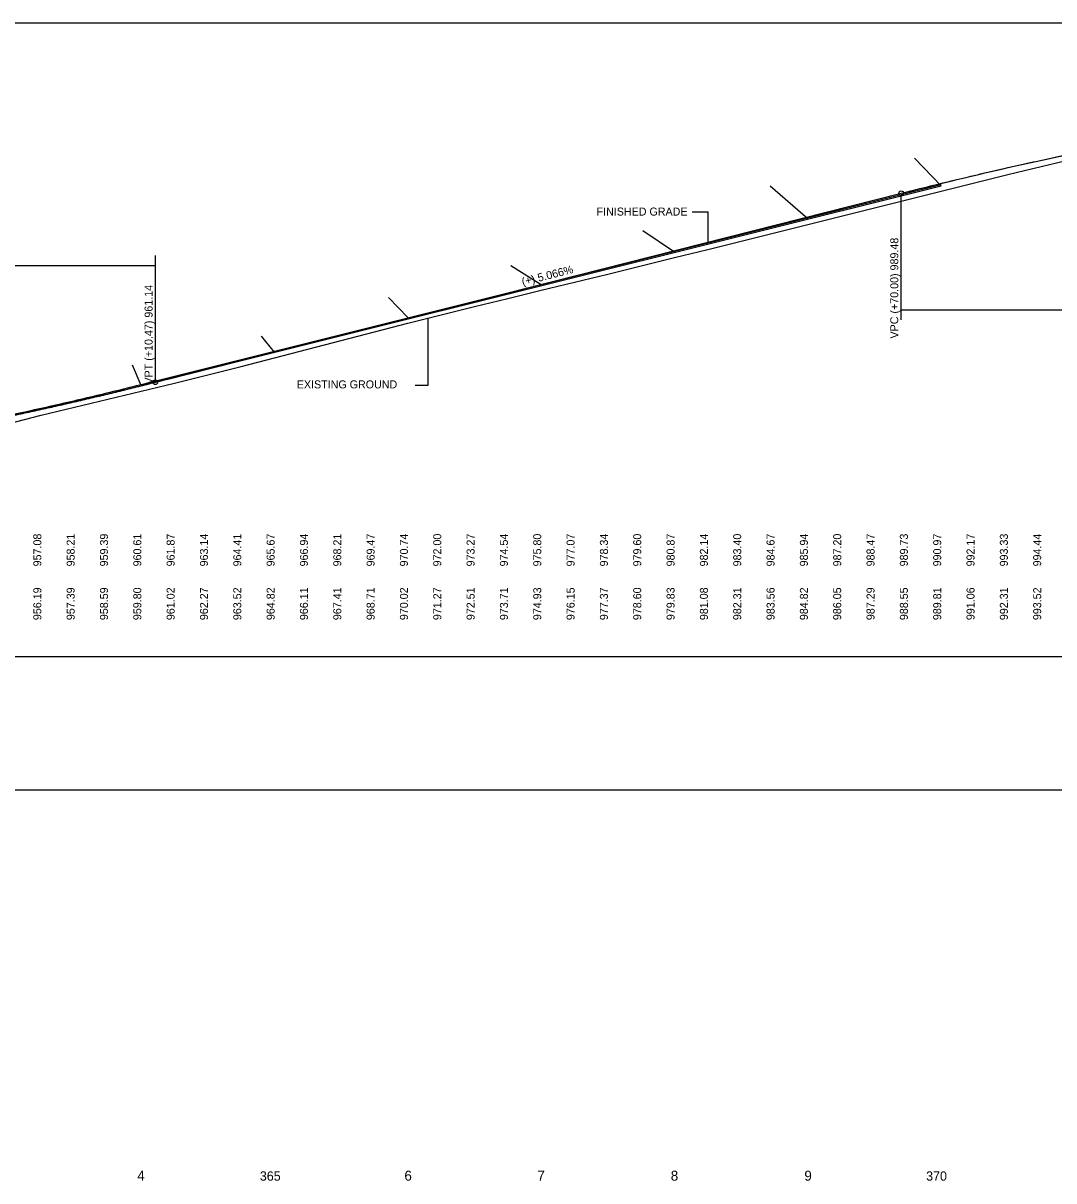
# Model space of a CAD drawing. Extents: x 120 to 1628239, y 505 to 1092823.
# Drawn here: x 1616850 to 1617623, y 1076164 to 1077032 of the extents above; entities that cross this region are included whole.
import ezdxf

# ---------------------------------------------------------------- set-up
doc = ezdxf.new("R2010")
doc.units = 0
for name, color, linetype in [('Default', 7, 'Continuous'), ('RD_DDB_EX_Tx', 7, 'Continuous'), ('RD_DDB_GradeTX', 7, 'Continuous'), ('RD_DDB_PR_Tx', 7, 'Continuous'), ('RD_DDB_Profile_EX', 7, 'Continuous'), ('RD_DDB_Profile_PR', 7, 'Continuous'), ('RD_DDB_StaTX', 7, 'Continuous'), ('RD_DDB_StripGrade', 7, 'Continuous'), ('RD_DDB_StripGrade_PR', 7, 'Continuous'), ('RD_DDB_VCLbl', 7, 'Continuous'), ('RD_GPK_Profile_Cell', 7, 'Continuous'), ('RD_PD_Final_TrvlWay', 7, 'Continuous')]:
    doc.layers.add(name, color=color, linetype=linetype)

msp = doc.modelspace()

# ---------------------------------------------------------------- linework, layer by layer
at = {"layer": 'Default'}
msp.add_line((1616958.64, 1076765.41), (1617508.64, 1076904.72), dxfattribs=at)
msp.add_lwpolyline([(1616238.64, 1076557.31), (1617738.64, 1076557.31), (1617738.64, 1077032.31), (1616238.64, 1077032.31)], close=True, dxfattribs=at)
for points in [[(1617508.64, 1076904.72), (1617728.64, 1076960.44), (1617948.64, 1076984.68)], [(1616318.64, 1076676.36), (1616638.64, 1076684.36), (1616958.64, 1076765.41)], [(1616320.44, 1076676.89), (1616631.44, 1076684.04), (1616942.44, 1076762.31)]]:
    msp.add_open_spline(points, degree=2, dxfattribs=at)
at = {"layer": 'RD_DDB_EX_Tx'}
for p, q in [((1617153.85, 1076760.9), (1617153.85, 1076811.21)), ((1617144.13, 1076760.9), (1617153.85, 1076760.9))]:
    msp.add_line(p, q, dxfattribs=at)
at = {"layer": 'RD_DDB_PR_Tx'}
for p, q in [((1617351.84, 1076890.84), (1617363.71, 1076890.84)), ((1617363.71, 1076890.84), (1617363.71, 1076868.06))]:
    msp.add_line(p, q, dxfattribs=at)
at = {"layer": 'RD_DDB_Profile_EX'}
for points in [[(1617038.64, 1076781.4), (1617063.64, 1076787.85), (1617088.64, 1076794.37), (1617113.64, 1076800.87), (1617138.64, 1076807.39), (1617163.64, 1076813.68), (1617188.64, 1076819.87), (1617213.64, 1076825.87), (1617238.64, 1076831.97), (1617263.64, 1076838.04), (1617288.64, 1076844.17), (1617313.64, 1076850.31), (1617338.64, 1076856.46), (1617363.64, 1076862.69), (1617388.64, 1076868.87), (1617413.64, 1076875.12), (1617438.64, 1076881.4), (1617463.64, 1076887.57), (1617488.64, 1076893.78), (1617513.64, 1076900.05), (1617538.64, 1076906.35), (1617563.64, 1076912.59), (1617588.64, 1076918.85), (1617613.64, 1076924.92), (1617638.64, 1076930.89)], [(1616838.64, 1076731.9), (1616863.64, 1076738.25), (1616888.64, 1076744.28), (1616913.64, 1076750.24), (1616938.64, 1076756.3), (1616963.64, 1076762.42), (1616988.64, 1076768.68), (1617013.64, 1076774.9), (1617038.64, 1076781.4)]]:
    msp.add_lwpolyline(points, dxfattribs=at)
at = {"layer": 'RD_DDB_Profile_PR'}
for p in [(1616949.11, 1076762.99), (1617438.64, 1076886.99)]:
    msp.add_line(p, (1617508.64, 1076904.72), dxfattribs=at)
for points in [[(1617508.64, 1076904.72), (1617517.44, 1076906.93), (1617526.24, 1076909.12), (1617535.04, 1076911.29), (1617543.84, 1076913.43), (1617552.64, 1076915.55), (1617561.44, 1076917.64), (1617570.24, 1076919.7), (1617579.04, 1076921.74), (1617587.84, 1076923.76), (1617596.64, 1076925.75), (1617605.44, 1076927.71), (1617614.24, 1076929.65), (1617623.04, 1076931.56), (1617631.84, 1076933.45), (1617640.64, 1076935.32), (1617649.44, 1076937.15), (1617658.24, 1076938.97), (1617667.04, 1076940.76), (1617675.84, 1076942.52), (1617684.64, 1076944.26), (1617693.44, 1076945.97), (1617702.24, 1076947.66), (1617711.04, 1076949.32), (1617719.84, 1076950.96), (1617728.64, 1076952.57), (1617737.44, 1076954.16), (1617746.24, 1076955.72), (1617755.04, 1076957.25), (1617763.84, 1076958.76), (1617772.64, 1076960.25), (1617781.44, 1076961.71), (1617790.24, 1076963.15), (1617799.04, 1076964.56), (1617807.84, 1076965.94), (1617816.64, 1076967.3), (1617825.44, 1076968.64), (1617834.24, 1076969.95), (1617843.04, 1076971.23), (1617851.84, 1076972.49), (1617860.64, 1076973.73), (1617869.44, 1076974.93), (1617878.24, 1076976.12), (1617887.04, 1076977.28), (1617895.84, 1076978.41), (1617904.64, 1076979.52), (1617913.44, 1076980.6), (1617922.24, 1076981.66), (1617931.04, 1076982.69), (1617939.84, 1076983.7), (1617948.64, 1076984.68)], [(1616328.18, 1076676.6), (1616340.59, 1076676.94), (1616353.01, 1076677.33), (1616365.43, 1076677.78), (1616377.85, 1076678.29), (1616390.27, 1076678.86), (1616402.69, 1076679.48), (1616415.11, 1076680.16), (1616427.52, 1076680.9), (1616439.94, 1076681.69), (1616452.36, 1076682.54), (1616464.78, 1076683.44), (1616477.2, 1076684.4), (1616489.62, 1076685.42), (1616502.04, 1076686.5), (1616514.46, 1076687.63), (1616526.87, 1076688.82), (1616539.29, 1076690.07), (1616551.71, 1076691.37), (1616564.13, 1076692.73), (1616576.55, 1076694.15), (1616588.97, 1076695.62), (1616601.39, 1076697.15), (1616613.8, 1076698.73), (1616626.22, 1076700.38), (1616638.64, 1076702.08), (1616651.06, 1076703.83), (1616663.48, 1076705.65), (1616675.9, 1076707.52), (1616688.32, 1076709.44), (1616700.73, 1076711.43), (1616713.15, 1076713.47), (1616725.57, 1076715.56), (1616737.99, 1076717.72), (1616750.41, 1076719.93), (1616762.83, 1076722.19), (1616775.25, 1076724.51), (1616787.67, 1076726.89), (1616800.08, 1076729.33), (1616812.5, 1076731.83), (1616824.92, 1076734.38), (1616837.34, 1076736.98), (1616849.76, 1076739.65), (1616862.18, 1076742.37), (1616874.6, 1076745.14), (1616887.01, 1076747.98), (1616899.43, 1076750.87), (1616911.85, 1076753.81), (1616924.27, 1076756.82), (1616936.69, 1076759.88), (1616949.11, 1076762.99)]]:
    msp.add_spline(points, degree=3, dxfattribs=at)
at = {"layer": 'RD_DDB_VCLbl'}
for p, q in [((1617508.64, 1076809.72), (1617508.64, 1076902.97)), ((1616949.11, 1076857.99), (1616949.11, 1076764.74)), ((1616328.18, 1076850.49), (1616949.11, 1076850.49)), ((1617508.64, 1076817.22), (1617948.64, 1076817.22))]:
    msp.add_line(p, q, dxfattribs=at)
for centre in [(1617508.64, 1076904.72), (1616949.11, 1076762.99)]:
    msp.add_circle(centre, 1.75, dxfattribs=at)
at = {"layer": 'RD_GPK_Profile_Cell'}
msp.add_line((1609538.64, 1076457.31), (1626874.64, 1076457.31), dxfattribs=at)
at = {"layer": 'RD_PD_Final_TrvlWay'}
for p, q in [((1617538.64, 1076910.41), (1617518.69, 1076930.94)), ((1616938.64, 1076761.36), (1617538.64, 1076911.26)), ((1616938.64, 1076760.51), (1617538.64, 1076910.41)), ((1616938.64, 1076760.51), (1617538.64, 1076910.41)), ((1617438.64, 1076885.51), (1617410.38, 1076909.94)), ((1617338.64, 1076860.61), (1617314.73, 1076876.48)), ((1617238.64, 1076836.11), (1617215.74, 1076850.37)), ((1617138.64, 1076811.51), (1617124.02, 1076826.66)), ((1617038.64, 1076785.66), (1617028.85, 1076797.59)), ((1616938.64, 1076760.51), (1616931.99, 1076775.73))]:
    msp.add_line(p, q, dxfattribs=at)

# ---------------------------------------------------------------- texts
at = {"layer": 'RD_DDB_EX_Tx'}
msp.add_text('EXISTING GROUND', height=6, dxfattribs=at).set_placement((1617055.26, 1076758.41))
at = {"layer": 'RD_DDB_GradeTX'}
msp.add_text('(+) 5.066%', height=6, rotation=14.21319, dxfattribs=at).set_placement((1617224.83, 1076835.34))
at = {"layer": 'RD_DDB_PR_Tx'}
msp.add_text('FINISHED GRADE', height=6, dxfattribs=at).set_placement((1617280.14, 1076888.01))
at = {"layer": 'RD_DDB_StaTX'}
for s, height, p in [('4', 7.5, (1616935.6, 1076164.25)), ('365', 7, (1617027.56, 1076164.25)), ('6', 7.5, (1617136, 1076164.25)), ('7', 7.5, (1617235.76, 1076164.25)), ('8', 7.5, (1617335.8, 1076164.25)), ('9', 7.5, (1617436, 1076164.25)), ('370', 7, (1617527.33, 1076164.25))]:
    msp.add_text(s, height=height, dxfattribs=at).set_placement(p)
at = {"layer": 'RD_DDB_StripGrade'}
for s, p in [('956.19', (1616863.64, 1076584.62)), ('957.39', (1616888.64, 1076584.62)), ('958.59', (1616913.64, 1076584.62)), ('959.80', (1616938.64, 1076584.62)), ('961.02', (1616963.64, 1076584.62)), ('962.27', (1616988.64, 1076584.62)), ('963.52', (1617013.64, 1076584.62)), ('964.82', (1617038.64, 1076584.62)), ('966.11', (1617063.64, 1076584.62)), ('967.41', (1617088.64, 1076584.62)), ('968.71', (1617113.64, 1076584.62)), ('970.02', (1617138.64, 1076584.62)), ('971.27', (1617163.64, 1076584.62)), ('972.51', (1617188.64, 1076584.62)), ('973.71', (1617213.64, 1076584.62)), ('974.93', (1617238.64, 1076584.62)), ('976.15', (1617263.64, 1076584.62)), ('977.37', (1617288.64, 1076584.62)), ('978.60', (1617313.64, 1076584.62)), ('979.83', (1617338.64, 1076584.62)), ('981.08', (1617363.64, 1076584.62)), ('982.31', (1617388.64, 1076584.62)), ('983.56', (1617413.64, 1076584.62)), ('984.82', (1617438.64, 1076584.62)), ('986.05', (1617463.64, 1076584.62)), ('987.29', (1617488.64, 1076584.62)), ('988.55', (1617513.64, 1076584.62)), ('989.81', (1617538.64, 1076584.62)), ('991.06', (1617563.64, 1076584.62)), ('992.31', (1617588.64, 1076584.62)), ('993.52', (1617613.64, 1076584.62))]:
    msp.add_text(s, height=6, rotation=90, dxfattribs=at).set_placement(p)
at = {"layer": 'RD_DDB_StripGrade_PR'}
for s, p in [('957.08', (1616863.64, 1076624.93)), ('958.21', (1616888.64, 1076624.93)), ('959.39', (1616913.64, 1076624.93)), ('960.61', (1616938.64, 1076624.93)), ('961.87', (1616963.64, 1076624.93)), ('963.14', (1616988.64, 1076624.93)), ('964.41', (1617013.64, 1076624.93)), ('965.67', (1617038.64, 1076624.93)), ('966.94', (1617063.64, 1076624.93)), ('968.21', (1617088.64, 1076624.93)), ('969.47', (1617113.64, 1076624.93)), ('970.74', (1617138.64, 1076624.93)), ('972.00', (1617163.64, 1076624.93)), ('973.27', (1617188.64, 1076624.93)), ('974.54', (1617213.64, 1076624.93)), ('975.80', (1617238.64, 1076624.93)), ('977.07', (1617263.64, 1076624.93)), ('978.34', (1617288.64, 1076624.93)), ('979.60', (1617313.64, 1076624.93)), ('980.87', (1617338.64, 1076624.93)), ('982.14', (1617363.64, 1076624.93)), ('983.40', (1617388.64, 1076624.93)), ('984.67', (1617413.64, 1076624.93)), ('985.94', (1617438.64, 1076624.94)), ('987.20', (1617463.64, 1076624.94)), ('988.47', (1617488.64, 1076624.94)), ('989.73', (1617513.64, 1076624.94)), ('990.97', (1617538.64, 1076624.94)), ('992.17', (1617563.64, 1076624.94)), ('993.33', (1617588.64, 1076624.94)), ('994.44', (1617613.64, 1076624.94))]:
    msp.add_text(s, height=6, rotation=90, dxfattribs=at).set_placement(p)
at = {"layer": 'RD_DDB_VCLbl'}
for s, p in [('VPC (+70.00) 989.48', (1617506.45, 1076795.8)), ('VPT (+10.47) 961.14', (1616947.11, 1076761.29))]:
    msp.add_text(s, height=6, rotation=90, dxfattribs=at).set_placement(p)

doc.saveas('drawing.dxf')
